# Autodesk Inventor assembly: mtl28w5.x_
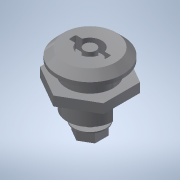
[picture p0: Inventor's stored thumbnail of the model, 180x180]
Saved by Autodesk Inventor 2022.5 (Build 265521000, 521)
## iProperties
Part Number: mtl28w5.x_
Material: 一般
Document SubType Name: Assembly
Designer: ImaoCorp
Sending System: SOLIDWORKS 2017-2017317
MC: AMD64
MC_MODEL: Intel64 Family 6 Model 60 Stepping 3, GenuineIntel
OS: Windows_NT
FRU: Parasolid Version 29.0, build 201,  4-17-2017
FORMAT: text
GUISE: transmit
KEY: mtl28w5
FILE: mtl28w5.x_t
DATE: Fri Jul 26 11:49:22 2019
Author: ImaoCorp
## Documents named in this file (4)
- X:\14_SW2022-Inv2022\00_全2023-1023新製品(TCC)まで\m\mtl28w5\MTL28W5.iam
- X:\14_SW2022-Inv2022\00_全2023-1023新製品(TCC)まで\m\mtl28w5\mtl28w5_01.ipt
- X:\14_SW2022-Inv2022\00_全2023-1023新製品(TCC)まで\m\mtl28w5\mtl28w5_02.ipt
- X:\14_SW2022-Inv2022\00_全2023-1023新製品(TCC)まで\m\mtl28w5\mtl28w5_03.ipt
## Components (3 placed, 3 different names)
1. mtl28w5_01
2. mtl28w5_02
3. mtl28w5_03
